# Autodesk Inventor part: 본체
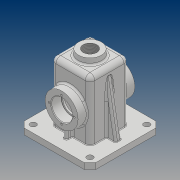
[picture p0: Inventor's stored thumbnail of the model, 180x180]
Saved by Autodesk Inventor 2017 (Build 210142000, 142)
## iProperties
Part Number: 본체
Material: 일반
Document SubType Name: Modeling
Designer: 20
Density: 1 g/cm^3
Appearance: 기본값
Author: 20
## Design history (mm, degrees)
sketch "스케치1"
  geometry: L1 (-32.5, 32.5)-(32.5, 32.5); L2 (32.5, 32.5)-(32.5, -32.5); L3 (32.5, -32.5)-(-32.5, -32.5); L4 (-32.5, -32.5)-(-32.5, 32.5); L5 (-32.5, 32.5)-(32.5, -32.5); L6 (32.5, 32.5)-(-32.5, -32.5); 1 further point
  constraints: 12 end point, 2 midpoint, 2 parallel, 1 horizontal, 1 perpendicular
  dimensions: "d0" = 65 distance of L2.end L3.end; "d1" = 65 distance of L1.end L2.end
extrude "돌출1" new body sketch "스케치1" distance "d2" = 110; taper "d3" = 0 deg
fillet "모깎기1" dims "d4" = 8
feature "쉘1" dims "d5" = 5
sketch "스케치2"
  geometry: L1 (60, -60)-(-60, -60); L2 (-60, -60)-(-60, 60); L3 (-60, 60)-(60, 60); L4 (60, 60)-(60, -60); L5 (60, -60)-(-60, 60); L6 (-60, -60)-(60, 60); L7 (24.5, -27.5)-(-24.5, -27.5) reference; L8 (-27.5, -24.5)-(-27.5, 24.5) reference; L9 (-24.5, 27.5)-(24.5, 27.5) reference; L10 (27.5, 24.5)-(27.5, -24.5) reference; L11 (-32.5, 24.5)-(-32.5, -24.5) reference; L12 (-24.5, -32.5)-(24.5, -32.5) reference; L13 (32.5, -24.5)-(32.5, 24.5) reference; L14 (24.5, 32.5)-(-24.5, 32.5) reference; A1 r 3 centre (24.5, -24.5) between (24.5, -27.5) and (27.5, -24.5) reference; A2 r 3 centre (-24.5, -24.5) between (-27.5, -24.5) and (-24.5, -27.5) reference; A3 r 3 centre (-24.5, 24.5) between (-24.5, 27.5) and (-27.5, 24.5) reference; A4 r 3 centre (24.5, 24.5) between (27.5, 24.5) and (24.5, 27.5) reference; A5 r 8 centre (-24.5, 24.5) between (-24.5, 32.5) and (-32.5, 24.5) reference; A6 r 8 centre (-24.5, -24.5) between (-32.5, -24.5) and (-24.5, -32.5) reference; A7 r 8 centre (24.5, -24.5) between (24.5, -32.5) and (32.5, -24.5) reference; A8 r 8 centre (24.5, 24.5) between (32.5, 24.5) and (24.5, 32.5) reference; 1 further point
  constraints: 12 end point, 2 midpoint, 2 parallel, 1 horizontal, 1 perpendicular
  dimensions: "d6" = 120 distance of L2.end L3.end; "d7" = 120 distance of L1.end L2.end
extrude "돌출2" join sketch "스케치2" distance "d8" = 10; taper "d9" = 0 deg
chamfer "모따기1" distance "d10" = 10; stored, may be unused: second distance "d11" = 2, angle "d12" = 45 deg
sketch "스케치3"
  geometry: L1 (-25.5, -102)-(74.5, -102) reference; C1 r 27.5 at (24.5, -47); 2 further points
  constraints: 1 centre point, 1 midpoint, 1 vertical alignment
  dimensions: "d13" = 55 diameter of C1; "d14" = 55 distance from line of L1 C1.centre
extrude "돌출3" join sketch "스케치3" distance "d15" = 15; taper "d16" = 0 deg
sketch "스케치4"
  geometry: L1 (24.5, 47)-(24.5, 12.49) reference; L2 (-24.5, 47)-(24.5, 47) reference; L3 (-24.5, 12.49)-(-24.5, 47) reference; C1 r 17.5 at (0, 0); A1 r 27.5 centre (0, 0) between (24.5, 12.49) and (-24.5, 12.49) reference; A2 r 27.5 centre (0, 0) between (-24.5, 12.49) and (24.5, 12.49) reference; 1 further point
  constraints: 1 centre point, 1 coincident
  dimensions: "d17" = 35 diameter of C1
extrude "돌출4" cut sketch "스케치4" distance "d18" = 17; taper "d19" = 0 deg
sketch "스케치5"
  geometry: C1 r 15 at (0, 0); C2 r 17.5 at (0, 0) reference; 1 further point
  constraints: 1 centre point, 1 concentric
  dimensions: "d20" = 30 diameter of C1
extrude "돌출5" cut sketch "스케치5" distance "d21" = 3; taper "d22" = 0 deg
sketch "스케치6"
  geometry: C1 r 17.5 at (0, 0) reference; 2 further points
  constraints: 1 horizontal alignment
  dimensions: "d23" = 21 distance of C1.centre point (-21, 0)
hole "구멍1" sketch "스케치6" at (-21, 0) diameter "d24" = 3.242; stored, may be unused: countersink angle "d28" = 90 deg, drill point angle "d30" = 118 deg; dims "d25" = 8, "d26" = 4, "d27" = 2, "d29" = 10
node "작업 평면1"
sketch "스케치7"
  geometry: C1 r 20 at (0, 0); 1 further point
  constraints: 1 centre point, 1 coincident
  dimensions: "d35" = 40 diameter of C1
extrude "돌출6" join sketch "스케치7" stored distance "d36" = 10; taper "d37" = 0 deg
feature "면 기울기1" dims angle "d38" = 5 deg
hole "구멍2" diameter "d41" = 22.835; stored, may be unused: countersink angle "d45" = 90 deg, drill point angle "d47" = 118 deg; dims "d39" = 10, "d40" = 10, "d42" = 50, "d43" = 4, "d44" = 2, "d46" = 59.3
sketch "스케치8"
  geometry: L1 (-3, -27.5)-(3, -27.5); L2 (3, -27.5)-(3, -42.5); L3 (3, -42.5)-(-3, -42.5); L4 (-3, -42.5)-(-3, -27.5); L5 (-24.5, -27.5)-(24.5, -27.5) reference; 1 further point
  constraints: 8 end point, 2 parallel, 1 horizontal, 1 perpendicular
  dimensions: "d48" = 6 distance of L2.end L3.end; "d49" = 0 distance between parallel lines of L1 L5; "d50" = 3 distance from line of point (0, 0) L4; "d51" = 15 distance between parallel lines of L3 L5
extrude "돌출7" join sketch "스케치8" stored distance "d52" = 10; taper "d53" = 0 deg
sketch "스케치9"
  geometry: C1 r 5 at (-47.5, 47.5); 1 further point
  constraints: 1 centre point
  dimensions: "d54" = 10 diameter of C1; "d55" = 47.5 horizontal distance of point (0, 0) C1.centre; "d56" = 47.5 horizontal distance of point (0, 0) C1.centre
extrude "돌출8" cut sketch "스케치9" distance "d57" = 10; taper "d58" = 0 deg
sketch "스케치10"
  geometry: L1 (37.42, 70)-(48, 10); L2 (60, 10)-(50, 10) reference; L3 (-50, 10)-(50, 10) reference; L4 (60, 0)-(60, 10) reference; 1 further point
  constraints: 2 end point, 1 point on line
  dimensions: "d59" = 10 deg angle of L1 L4; "d60" = 12 distance of L1.end L2.start; "d61" = 60 vertical distance of L1.start L1.end
feature "리브1" sketch "스케치10" dims "d62" = 1, "d63" = 10, "d64" = 0, "d65" = 0, "d66" = 1, "d67" = 1
fillet "모깎기2" dims "d68" = 3
fillet "모깎기3" dims "d69" = 0.3
fillet "모깎기4" dims "d70" = 3
fillet "모깎기5" dims "d71" = 3
fillet "모깎기6" dims "d72" = 3
fillet "모깎기7" dims "d73" = 3
fillet "모깎기8" dims "d74" = 3
fillet "모깎기9" dims "d75" = 1
fillet "모깎기10" dims "d76" = 3
fillet "모깎기11" dims "d77" = 3
node "작업 평면2"
sketch "스케치11"
  geometry: L1 (57, 0)-(57, 91) reference; L2 (43.625, -18)-(5.375, -18) reference; 2 further points
  constraints: 1 other
  dimensions: "d79" = 32.5 distance from line of point (24.5, 8) L1; "d80" = 26 distance from line of point (24.5, 8) L2
feature "엠보싱1" sketch "스케치11" dims "d6" = 120, "d7" = 120, "d81" = 0.5, "d82" = 0
chamfer "모따기2" distance "d83" = 1; stored, may be unused: second distance "d84" = 2, angle "d85" = 45 deg
node "솔리드1"
mirror "미러1"
pattern_circular "원형 패턴1" dims angle "d32" = 360 deg
mirror "미러2"
mirror "미러3"
mirror "미러4"
mirror "미러5"
mirror "미러6"
node "투영된 루프1"
node "투영된 루프2"
other parameters: "d78" = 32.5
